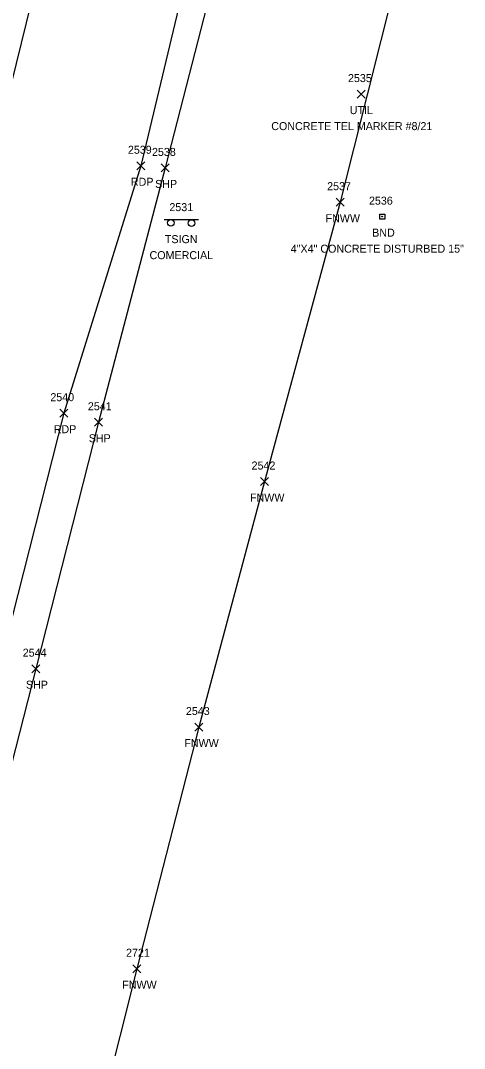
# Model space of a CAD drawing. Extents: x 1443071 to 1445292, y 614024 to 622563.
# Drawn here: x 1444166.6 to 1444277.6, y 620327.5 to 620584.3 of the extents above; entities that cross this region are included whole.
import ezdxf

# ---------------------------------------------------------------- set-up
doc = ezdxf.new("R2010")
doc.units = 0
for name, color, linetype in [('L_A', 7, 'Continuous'), ('L_I', 7, 'Continuous'), ('L_TIC', 7, 'Continuous'), ('LFNC', 7, 'Continuous'), ('M_A', 7, 'Continuous'), ('M_C', 7, 'Continuous'), ('M_I', 7, 'Continuous'), ('MHBP', 7, 'Continuous'), ('P_A', 7, 'Continuous'), ('P_I', 7, 'Continuous'), ('P_TIC', 7, 'Continuous'), ('PET', 7, 'Continuous'), ('PSP', 7, 'Continuous'), ('S_A', 7, 'Continuous'), ('S_C', 7, 'Continuous'), ('S_I', 7, 'Continuous'), ('SSGN', 7, 'Continuous'), ('U_A', 7, 'Continuous'), ('U_C', 7, 'Continuous'), ('U_I', 7, 'Continuous'), ('UDEFAULT', 7, 'Continuous')]:
    doc.layers.add(name, color=color, linetype=linetype)

msp = doc.modelspace()

# ---------------------------------------------------------------- linework, layer by layer
at = {"layer": 'L_TIC'}
for points in [[(1444245.55, 620537.96), (1444247.55, 620539.96)], [(1444247.55, 620537.96), (1444245.55, 620539.96)], [(1444226.66, 620468.15), (1444228.66, 620470.15)], [(1444228.66, 620468.15), (1444226.66, 620470.15)], [(1444210.24, 620406.8), (1444212.24, 620408.8)], [(1444212.24, 620406.8), (1444210.24, 620408.8)], [(1444194.72, 620346.39), (1444196.72, 620348.39)], [(1444196.72, 620346.39), (1444194.72, 620348.39)]]:
    msp.add_lwpolyline(points, dxfattribs=at)
at = {"layer": 'LFNC'}
msp.add_lwpolyline([(1444419.19, 620873.15), (1444374.8, 620882.12), (1444324.82, 620892.87), (1444313.12, 620833.07), (1444292.13, 620722.15), (1444270.22, 620633.1), (1444246.55, 620538.96), (1444227.66, 620469.15), (1444211.24, 620407.8), (1444195.72, 620347.39), (1444170.47, 620246.87)], dxfattribs=at)
at = {"layer": 'MHBP'}
msp.add_lwpolyline([(1444256.44, 620535.96), (1444257.69, 620535.96), (1444257.69, 620534.71), (1444256.44, 620534.71)], close=True, dxfattribs=at)
msp.add_circle((1444257.06, 620535.34), 0.0833, dxfattribs=at)
at = {"layer": 'P_TIC'}
for points in [[(1444195.75, 620547.06), (1444197.75, 620549.06)], [(1444197.75, 620547.06), (1444195.75, 620549.06)], [(1444201.76, 620546.52), (1444203.76, 620548.52)], [(1444203.76, 620546.52), (1444201.76, 620548.52)], [(1444176.44, 620485.23), (1444178.44, 620487.23)], [(1444178.44, 620485.23), (1444176.44, 620487.23)], [(1444185.16, 620482.96), (1444187.16, 620484.96)], [(1444187.16, 620482.96), (1444185.16, 620484.96)], [(1444169.45, 620421.38), (1444171.45, 620423.38)], [(1444171.45, 620421.38), (1444169.45, 620423.38)]]:
    msp.add_lwpolyline(points, dxfattribs=at)
at = {"layer": 'PET'}
for points in [[(1444393.99, 621275.61), (1444360.23, 621155.32), (1444345.74, 621103.98), (1444299.41, 620941.8), (1444273.27, 620844.52), (1444244.09, 620730.97), (1444221.37, 620651.37), (1444196.75, 620548.06), (1444177.44, 620486.23), (1444161.6, 620423.84), (1444143.45, 620356.38), (1444122.97, 620254.68), (1444105.94, 620160.17), (1444094.56, 620089.52), (1444083.91, 620011.71), (1444077.6, 619958.52), (1444073.05, 619913.75)], [(1444350.41, 621238.76), (1444319.14, 621126.97), (1444291.55, 621028.33), (1444258.02, 620908.98), (1444225.45, 620794.19), (1444210.22, 620737.59), (1444176.75, 620619.09), (1444153.1, 620523.45), (1444139.28, 620467.17), (1444131.97, 620435.45), (1444113.12, 620363.38), (1444103.37, 620315.76), (1444093.47, 620268.1), (1444084.86, 620222.29), (1444073.72, 620159.9), (1444065.08, 620092.83), (1444054.27, 620016.44), (1444048.57, 619960.86), (1444043.42, 619916.17), (1444073.05, 619913.75)]]:
    msp.add_lwpolyline(points, dxfattribs=at)
at = {"layer": 'PSP'}
msp.add_lwpolyline([(1444228.91, 620648.98), (1444202.76, 620547.52), (1444186.16, 620483.96), (1444170.45, 620422.38), (1444153.07, 620354.47), (1444132.16, 620257.26), (1444128.32, 620238.3), (1444112.75, 620158.8), (1444100.76, 620089.32), (1444087.94, 620010.71), (1444079.9, 619958.71), (1444074.06, 619920.41), (1444074.5, 619920), (1444074.51, 619919.99), (1444073.05, 619913.75)], dxfattribs=at)
at = {"layer": 'SSGN'}
for p, q in [((1444202.53, 620534.64), (1444211.12, 620534.64)), ((1444206.55, 620533.74), (1444206.55, 620533.74))]:
    msp.add_line(p, q, dxfattribs=at)
for centre in [(1444204.19, 620533.81), (1444209.4, 620533.74)]:
    msp.add_circle(centre, 0.833, dxfattribs=at)
at = {"layer": 'UDEFAULT'}
for points in [[(1444250.76, 620564.97), (1444252.76, 620566.97)], [(1444252.76, 620564.97), (1444250.76, 620566.97)]]:
    msp.add_lwpolyline(points, dxfattribs=at)

# ---------------------------------------------------------------- texts
at = {"layer": 'L_A'}
for p in [(1444242.89, 620533.96), (1444224, 620464.15), (1444207.58, 620402.8), (1444192.06, 620342.39)]:
    msp.add_text('FNWW', height=2, dxfattribs=at).set_placement(p)
at = {"layer": 'L_I'}
for s, p in [('2537', (1444243.29, 620541.96)), ('2542', (1444224.4, 620472.15)), ('2543', (1444207.98, 620410.8)), ('2721', (1444193.02, 620350.39))]:
    msp.add_text(s, height=2, dxfattribs=at).set_placement(p)
at = {"layer": 'M_A'}
msp.add_text('BND', height=2, dxfattribs=at).set_placement((1444254.55, 620530.34))
at = {"layer": 'M_C'}
msp.add_text('4"X4" CONCRETE DISTURBED 15"', height=2, dxfattribs=at).set_placement((1444234.2, 620526.34))
at = {"layer": 'M_I'}
msp.add_text('2536', height=2, dxfattribs=at).set_placement((1444253.75, 620538.34))
at = {"layer": 'P_A'}
for s, p in [('RDP', (1444194.23, 620543.06)), ('SHP', (1444200.29, 620542.52)), ('RDP', (1444174.93, 620481.23)), ('SHP', (1444183.69, 620478.96)), ('SHP', (1444167.98, 620417.38))]:
    msp.add_text(s, height=2, dxfattribs=at).set_placement(p)
at = {"layer": 'P_I'}
for s, p in [('2539', (1444193.48, 620551.06)), ('2538', (1444199.5, 620550.52)), ('2540', (1444174.09, 620489.23)), ('2541', (1444183.47, 620486.96)), ('2544', (1444167.19, 620425.38))]:
    msp.add_text(s, height=2, dxfattribs=at).set_placement(p)
at = {"layer": 'S_A'}
msp.add_text('TSIGN', height=2, dxfattribs=at).set_placement((1444202.72, 620528.72))
at = {"layer": 'S_C'}
msp.add_text('COMERCIAL', height=2, dxfattribs=at).set_placement((1444198.89, 620524.72))
at = {"layer": 'S_I'}
msp.add_text('2531', height=2, dxfattribs=at).set_placement((1444203.85, 620536.72))
at = {"layer": 'U_A'}
msp.add_text('UTIL', height=2, dxfattribs=at).set_placement((1444248.93, 620560.97))
at = {"layer": 'U_C'}
msp.add_text('CONCRETE TEL MARKER #8/21', height=2, dxfattribs=at).set_placement((1444229.32, 620556.97))
at = {"layer": 'U_I'}
msp.add_text('2535', height=2, dxfattribs=at).set_placement((1444248.5, 620568.97))

doc.saveas('drawing.dxf')
